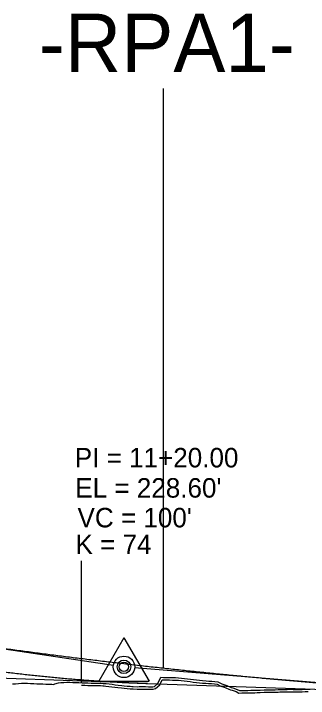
# Model space of a CAD drawing. Extents: x 2115752 to 2121174, y 562881 to 567245.
# Drawn here: x 2120214 to 2120289.6, y 564248.9 to 564424.5 of the extents above; entities that cross this region are included whole.
import ezdxf

# ---------------------------------------------------------------- set-up
doc = ezdxf.new("R2010")
doc.units = 0
for name, color, linetype in [('Exist Vertical Profile Ground Line', 7, 'Continuous'), ('Prop PFL VPI Symbol CELL', 7, 'Continuous'), ('Prop Vertical Profile Curve Label', 7, 'Continuous'), ('Prop Vertical Profile Grade', 7, 'Continuous'), ('Prop VPI Label', 7, 'Continuous'), ('Scratch_Level_1', 7, 'Continuous'), ('Scratch_Level_2', 7, 'Continuous')]:
    doc.layers.add(name, color=color, linetype=linetype)

msp = doc.modelspace()

# ---------------------------------------------------------------- linework, layer by layer
at = {"layer": 'Exist Vertical Profile Ground Line'}
for points in [[(2120218.357627, 564252.6780950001), (2120219.132216, 564252.6436999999), (2120219.9068050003, 564252.6103699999), (2120220.681394, 564252.578125), (2120221.455983, 564252.5469549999), (2120222.230572, 564252.5168699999), (2120223.005161, 564252.4878700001), (2120223.77975, 564252.4599649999), (2120224.220236, 564252.444715), (2120224.554339, 564252.5516049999), (2120225.544741, 564252.8633399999), (2120226.1035160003, 564252.8968450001), (2120226.878105, 564252.9440349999), (2120227.652694, 564252.9785349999), (2120228.027834, 564252.9805599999), (2120228.427283, 564252.97381), (2120229.201872, 564252.96145), (2120229.5677630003, 564252.9559599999), (2120229.9764610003, 564252.939905), (2120230.75105, 564252.910035), (2120231.557947, 564252.87208), (2120232.300228, 564252.8361849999), (2120233.074817, 564252.797175), (2120233.849406, 564252.76726), (2120234.623995, 564252.7681699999), (2120235.097685, 564252.7694499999), (2120235.3985840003, 564252.769535), (2120236.339904, 564252.771565), (2120236.947761, 564252.7020749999), (2120237.318392, 564252.6601), (2120237.72235, 564252.6198349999), (2120238.496939, 564252.5437350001), (2120239.271528, 564252.45991), (2120240.0461170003, 564252.3568549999), (2120240.820706, 564252.25481), (2120241.721504, 564252.13825), (2120242.369884, 564252.0842599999), (2120243.144473, 564252.0205799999), (2120243.9190620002, 564251.957725), (2120244.340274, 564251.924), (2120244.693651, 564251.9027849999), (2120245.669017, 564251.8455899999), (2120246.242829, 564251.8512500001), (2120247.017417, 564251.8593550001), (2120247.792006, 564251.86098), (2120248.566595, 564251.8235099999), (2120249.710114, 564251.7984499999), (2120250.1157730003, 564251.9127649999), (2120251.0239750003, 564252.6854549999), (2120251.747422, 564254.2491749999), (2120252.43954, 564254.229125), (2120253.213752, 564254.2074399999), (2120253.9879650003, 564254.1865000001), (2120254.7621770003, 564254.1705299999), (2120255.53639, 564254.1621), (2120256.3366360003, 564254.15201), (2120257.084814, 564254.0525900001), (2120257.859027, 564253.951665), (2120258.633239, 564253.8527099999), (2120259.4074520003, 564253.7557249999), (2120260.1816640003, 564253.6607349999), (2120260.955877, 564253.56774), (2120261.730089, 564253.4816549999), (2120262.504301, 564253.4115700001), (2120263.368935, 564253.3357449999), (2120264.052726, 564253.2953649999), (2120264.8269390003, 564253.251665), (2120265.6011510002, 564253.212755), (2120266.375364, 564253.079685), (2120267.437978, 564252.5892449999), (2120268.212288, 564252.31139), (2120268.698001, 564252.1133699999), (2120269.472213, 564251.806895), (2120269.845937, 564251.634395), (2120270.2464260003, 564251.51438), (2120271.3437260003, 564251.1638049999), (2120271.973299, 564250.8258999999), (2120272.569063, 564250.8559500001), (2120273.035769, 564250.8688599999), (2120274.117488, 564250.8946349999), (2120274.8917, 564250.9154749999), (2120275.8904750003, 564250.93402), (2120276.440125, 564250.9570449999), (2120277.252731, 564250.9927899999), (2120278.269526, 564251.026795), (2120278.7627620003, 564251.0344450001), (2120279.814172, 564251.053235), (2120280.311187, 564251.062255), (2120281.0854, 564251.07774), (2120281.8676360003, 564251.09486), (2120282.294633, 564251.1082499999), (2120282.961426, 564251.1286599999), (2120283.4080370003, 564251.133875), (2120284.1822490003, 564251.15021), (2120285.088724, 564251.1675849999), (2120285.730674, 564251.157605), (2120286.504887, 564251.147165), (2120287.442968, 564251.13679), (2120288.053311, 564251.1619699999), (2120288.8275240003, 564251.1952849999), (2120289.6017360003, 564251.22133)], [(2120213.710094, 564252.570545), (2120214.4846820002, 564252.6191649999), (2120215.259271, 564252.66962), (2120216.0338600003, 564252.72191), (2120216.808449, 564252.7501), (2120217.583038, 564252.713565), (2120218.357627, 564252.6780950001)], [(2120289.6017360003, 564251.22133), (2120290.070727, 564251.2379699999)]]:
    msp.add_lwpolyline(points, dxfattribs=at)
at = {"layer": 'Prop PFL VPI Symbol CELL'}
for p, q in [((2120242.301600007, 564264.4183000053), (2120235.8516000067, 564253.2183000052)), ((2120242.301600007, 564264.4183000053), (2120248.801600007, 564253.2183000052)), ((2120235.8516000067, 564253.2183000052), (2120248.801600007, 564253.2183000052))]:
    msp.add_line(p, q, dxfattribs=at)
for radius in [1.75, 1.2000000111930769]:
    msp.add_circle((2120242.3086, 564256.9363), radius, dxfattribs=at)
at = {"layer": 'Prop Vertical Profile Grade'}
msp.add_spline([(2120192.3086, 564264.4363), (2120194.3086, 564264.1376465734), (2120196.3086, 564263.8416862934), (2120198.3086, 564263.5484191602), (2120200.3086, 564263.2578451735), (2120202.3086, 564262.9699643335), (2120204.3086, 564262.6847766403), (2120206.3086, 564262.4022820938), (2120208.3086, 564262.1224806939), (2120210.3086, 564261.8453724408), (2120212.3086, 564261.5709573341), (2120214.3086, 564261.2992353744), (2120216.3086, 564261.0302065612), (2120218.3086, 564260.7638708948), (2120220.3086, 564260.5002283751), (2120222.3086, 564260.239279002), (2120224.3086, 564259.9810227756), (2120226.3086, 564259.7254596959), (2120228.3086, 564259.4725897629), (2120230.3086, 564259.2224129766), (2120232.3086, 564258.9749293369), (2120234.3086, 564258.730138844), (2120236.3086, 564258.4880414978), (2120238.3086, 564258.2486372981), (2120240.3086, 564258.0119262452), (2120242.3086, 564257.7779083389), (2120244.3086, 564257.5465835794), (2120246.3086, 564257.3179519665), (2120248.3086, 564257.0920135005), (2120250.3086, 564256.868768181), (2120252.3086, 564256.6482160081), (2120254.3086, 564256.430356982), (2120256.3086, 564256.2151911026), (2120258.3086, 564256.0027183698), (2120260.3086, 564255.7929387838), (2120262.3086, 564255.5858523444), (2120264.3086, 564255.3814590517), (2120266.3086, 564255.1797589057), (2120268.3086, 564254.9807519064), (2120270.3086, 564254.7844380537), (2120272.3086, 564254.5908173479), (2120274.3086, 564254.3998897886), (2120276.3086, 564254.211655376), (2120278.3086, 564254.02611411), (2120280.3086, 564253.8432659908), (2120282.3086, 564253.6631110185), (2120284.3086, 564253.4856491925), (2120286.3086, 564253.3108805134), (2120288.3086, 564253.1388049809), (2120290.3086, 564252.9694225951), (2120292.3086, 564252.802733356)], degree=3, dxfattribs=at)
at = {"layer": 'Prop VPI Label'}
for p, q in [((2120192.3086, 564264.4363), (2120239.58902503, 564257.3442362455)), ((2120292.3086, 564252.802733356), (2120245.0492503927, 564256.709726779))]:
    msp.add_line(p, q, dxfattribs=at)
msp.add_circle((2120242.3086, 564256.9363), 2.75, dxfattribs=at)
at = {"layer": 'Scratch_Level_1'}
for p, q in [((2120252.438606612, 564256.6339725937), (2120252.438606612, 564405.3290151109)), ((2120231.3686066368, 564252.881285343), (2120231.3686066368, 564284.108207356))]:
    msp.add_line(p, q, dxfattribs=at)
msp.add_lwpolyline([(2120231.3686066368, 564252.2555057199), (2120232.269415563, 564252.2119446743), (2120233.0470378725, 564252.1727819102), (2120233.8377085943, 564252.1422458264), (2120234.6252065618, 564252.143170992), (2120235.0986177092, 564252.1444502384), (2120235.3993461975, 564252.1445351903), (2120236.3049668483, 564252.1464882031), (2120236.877100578, 564252.0810820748), (2120237.252227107, 564252.0385979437), (2120237.660800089, 564251.9978729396), (2120238.4327607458, 564251.922031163), (2120239.196681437, 564251.8393606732), (2120239.964087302, 564251.7372613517), (2120240.739787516, 564251.6350699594), (2120241.6554357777, 564251.5165883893), (2120242.3183474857, 564251.4613883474), (2120243.0935931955, 564251.3976543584), (2120243.868845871, 564251.3347455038), (2120244.2966014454, 564251.3004965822), (2120244.656630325, 564251.2788822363), (2120245.653788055, 564251.2204093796), (2120246.2491810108, 564251.2262822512), (2120247.0213423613, 564251.2343618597), (2120247.7775531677, 564251.2359483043), (2120248.5446452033, 564251.1988409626), (2120249.789767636, 564251.1715543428), (2120250.4167508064, 564251.3482386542), (2120251.53355564, 564252.2984060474), (2120252.1415127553, 564253.6124963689), (2120252.4217415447, 564253.6043784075), (2120253.1965535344, 564253.5826766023), (2120253.9730711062, 564253.561674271), (2120254.7523296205, 564253.5456001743), (2120255.529047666, 564253.5371428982), (2120256.291370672, 564253.527531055), (2120257.0032546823, 564253.4329339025), (2120257.7790122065, 564253.3318075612), (2120258.55477634, 564253.2326541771), (2120259.3305528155, 564253.1354733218), (2120260.1063396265, 564253.0402901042), (2120260.8840731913, 564252.9468722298), (2120261.667374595, 564252.8597765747), (2120262.4488270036, 564252.7890361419), (2120263.323203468, 564252.7123567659), (2120264.016693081, 564252.6714040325), (2120264.7936421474, 564252.6275495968), (2120265.532282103, 564252.5904273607), (2120266.188275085, 564252.4776767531), (2120267.2010162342, 564252.0102551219), (2120267.988663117, 564251.7276142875), (2120268.464999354, 564251.5334170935), (2120269.226039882, 564251.2321560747), (2120269.6241631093, 564251.0483941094), (2120270.061600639, 564250.917306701), (2120271.098784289, 564250.5859381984), (2120271.831025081, 564250.1929292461), (2120272.5934495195, 564250.2313855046), (2120273.0518541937, 564250.2440658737), (2120274.13334085, 564250.2698353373), (2120274.905910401, 564250.2906311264), (2120275.9093582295, 564250.3092628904), (2120276.4669372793, 564250.3326200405), (2120277.2769098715, 564250.368249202), (2120278.284818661, 564250.4019570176), (2120278.7731921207, 564250.4095316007), (2120279.8254262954, 564250.4283363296), (2120280.3231064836, 564250.4373684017), (2120281.0984867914, 564250.452876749), (2120281.884268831, 564250.4700743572), (2120282.3139886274, 564250.4835497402), (2120282.9746368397, 564250.5037716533), (2120283.4182779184, 564250.5089519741), (2120284.1948297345, 564250.5253363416), (2120285.0898554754, 564250.5424918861), (2120285.7216027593, 564250.5326705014), (2120286.4972174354, 564250.5222116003), (2120287.45239985, 564250.5116474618), (2120288.079627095, 564250.5375240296), (2120288.851465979, 564250.5707368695), (2120289.6227495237, 564250.5966833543)], dxfattribs=at)
at = {"layer": 'Scratch_Level_2'}
for q in [(2120208.0569151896, 564254.0900522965), (2120357.3086, 564248.8631656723)]:
    msp.add_line((2120248.3086, 564252.6804133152), q, dxfattribs=at)
msp.add_spline([(2120162.3086, 564264.9363), (2120164.0286000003, 564264.5099976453), (2120165.7486, 564264.0910905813), (2120167.4686000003, 564263.679578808), (2120169.1886, 564263.2754623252), (2120170.9086, 564262.8787411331), (2120172.6286, 564262.4894152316), (2120174.3486, 564262.107484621), (2120176.0686, 564261.7329493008), (2120177.7886, 564261.3658092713), (2120179.5086000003, 564261.0060645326), (2120181.2286, 564260.6537150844), (2120182.9486000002, 564260.308760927), (2120184.6686, 564259.97120206), (2120186.3886, 564259.6410384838), (2120188.1086, 564259.3182701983), (2120189.8286, 564259.0028972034), (2120191.5486000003, 564258.6949194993), (2120193.2686, 564258.3943370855), (2120194.9886000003, 564258.1011499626), (2120196.7086, 564257.8153581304), (2120198.4286, 564257.5369615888), (2120200.1486, 564257.2659603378), (2120201.8686, 564257.0023543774), (2120203.5886, 564256.7461437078), (2120205.3086, 564256.4973283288), (2120207.0286000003, 564256.2559082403), (2120208.7486, 564256.0218834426), (2120210.4686000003, 564255.7952539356), (2120212.1886, 564255.5760197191), (2120213.9086, 564255.3641807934), (2120215.6286, 564255.1597371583), (2120217.3486, 564254.9626888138), (2120219.0686, 564254.77303576), (2120220.7886, 564254.5907779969), (2120222.5086000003, 564254.4159155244), (2120224.2286, 564254.2484483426), (2120225.9486000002, 564254.0883764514), (2120227.6686, 564253.9356998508), (2120229.3886, 564253.790418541), (2120231.1086, 564253.6525325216), (2120232.8286, 564253.5220417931), (2120234.5486000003, 564253.3989463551), (2120236.2686, 564253.2832462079), (2120237.9886000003, 564253.1749413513), (2120239.7086, 564253.0740317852), (2120241.4286, 564252.98051751), (2120243.1486, 564252.8943985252), (2120244.8686, 564252.8156748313), (2120246.5886, 564252.7443464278), (2120248.3086, 564252.6804133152)], degree=3, dxfattribs=at)

# ---------------------------------------------------------------- texts
at = {"layer": 'Prop Vertical Profile Curve Label'}
for s, p in [("VC = 100'", (2120230.381513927, 564292.7178512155)), ('K = 74', (2120229.8783212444, 564285.8784644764))]:
    msp.add_text(s, height=5, dxfattribs=at).set_placement(p)
at = {"layer": 'Prop VPI Label'}
for s, p in [('PI = 11+20.00', (2120229.6784611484, 564308.1012642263)), ("EL = 228.60'", (2120229.8062889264, 564300.3515197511))]:
    msp.add_text(s, height=5, dxfattribs=at).set_placement(p)
at = {"layer": 'Scratch_Level_1'}
msp.add_text('-RPA1-', height=15, dxfattribs=at).set_placement((2120220.4383157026, 564409.5055438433))

doc.saveas('drawing.dxf')
